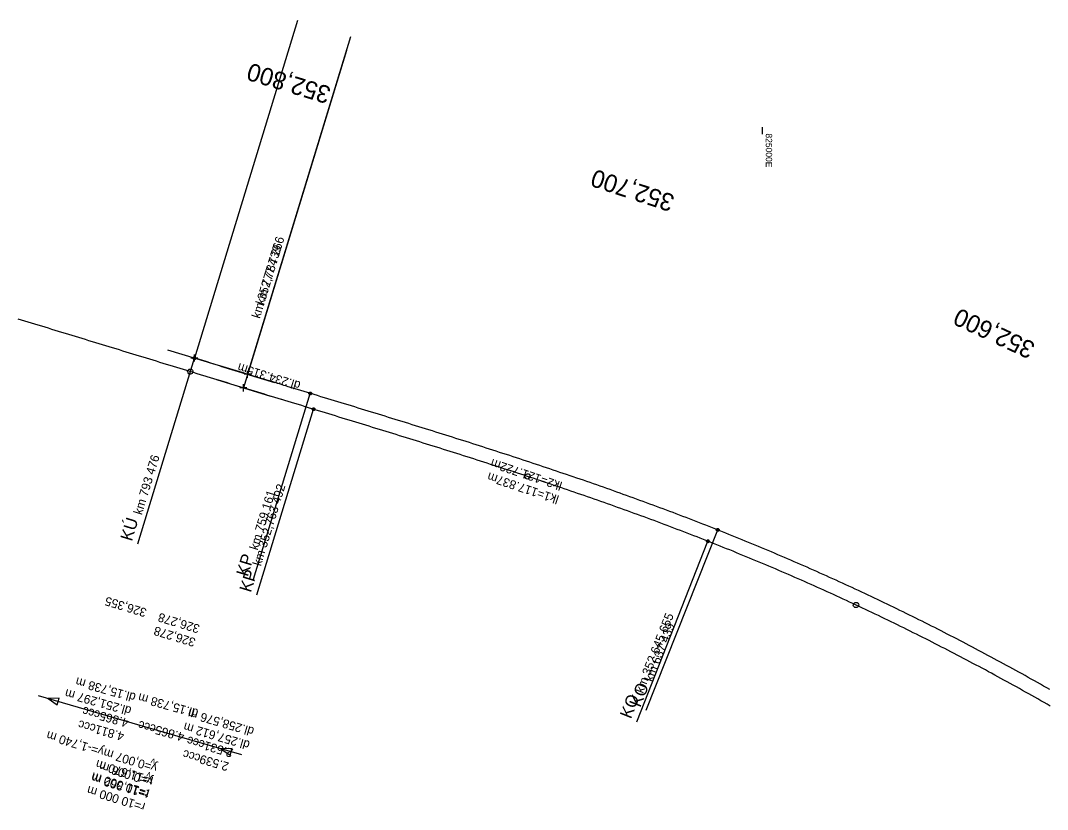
# Model space of a CAD drawing. Extents: x -825429 to 825387, y -1070027 to 1069917.
# Drawn here: x -825210.1 to -824919.2, y -1069630.4 to -1069406.8 of the extents above; entities that cross this region are included whole.
import ezdxf

# ---------------------------------------------------------------- set-up
doc = ezdxf.new("R2010")
doc.units = 0
for name, color, linetype in [('NEW KOLEJE PALKOBAR', 7, 'Continuous'), ('NEW KOLEJE VLADO', 7, 'Continuous'), ('NEW KOLEJE VLADO PROVI', 7, 'Continuous')]:
    doc.layers.add(name, color=color, linetype=linetype)

msp = doc.modelspace()

# ---------------------------------------------------------------- linework, layer by layer
at = {"layer": 'NEW KOLEJE PALKOBAR'}
for points in [[(-824918.47, -1069601.04), (-824919.33, -1069600.54), (-824920.2, -1069600.04), (-824921.07, -1069599.55), (-824921.94, -1069599.05), (-824922.81, -1069598.56), (-824923.68, -1069598.07), (-824924.55, -1069597.58), (-824925.42, -1069597.09), (-824926.3, -1069596.6), (-824927.17, -1069596.11), (-824928.04, -1069595.63), (-824928.92, -1069595.14), (-824929.79, -1069594.66), (-824930.67, -1069594.18), (-824931.55, -1069593.7), (-824932.42, -1069593.22), (-824933.3, -1069592.74), (-824934.18, -1069592.26), (-824935.06, -1069591.78), (-824935.94, -1069591.31), (-824936.82, -1069590.83), (-824937.7, -1069590.36), (-824938.58, -1069589.89), (-824939.46, -1069589.42), (-824940.35, -1069588.95), (-824941.23, -1069588.48), (-824942.11, -1069588.01), (-824943, -1069587.55), (-824943.89, -1069587.08), (-824944.77, -1069586.62), (-824945.66, -1069586.16), (-824946.55, -1069585.7), (-824947.43, -1069585.24), (-824948.32, -1069584.78), (-824949.21, -1069584.32), (-824950.1, -1069583.87), (-824950.99, -1069583.41), (-824951.88, -1069582.96), (-824952.77, -1069582.5), (-824953.67, -1069582.05), (-824954.56, -1069581.6), (-824955.45, -1069581.15), (-824956.35, -1069580.71), (-824957.24, -1069580.26), (-824958.14, -1069579.81), (-824959.03, -1069579.37), (-824959.93, -1069578.93), (-824960.83, -1069578.49), (-824961.73, -1069578.05), (-824962.62, -1069577.61), (-824963.52, -1069577.17), (-824964.42, -1069576.73), (-824965.32, -1069576.3), (-824966.22, -1069575.86), (-824967.12, -1069575.43), (-824968.03, -1069575), (-824968.93, -1069574.57), (-824969.83, -1069574.14), (-824970.74, -1069573.71), (-824971.64, -1069573.28), (-824972.54, -1069572.85), (-824973.45, -1069572.43), (-824974.36, -1069572.01), (-824975.26, -1069571.58), (-824976.17, -1069571.16), (-824977.08, -1069570.74), (-824977.99, -1069570.33), (-824978.89, -1069569.91), (-824979.8, -1069569.49), (-824980.71, -1069569.08), (-824981.62, -1069568.66), (-824982.54, -1069568.25), (-824983.45, -1069567.84), (-824984.36, -1069567.43), (-824985.27, -1069567.02), (-824986.18, -1069566.61), (-824987.1, -1069566.21), (-824988.01, -1069565.8), (-824988.93, -1069565.4), (-824989.84, -1069565), (-824990.76, -1069564.6), (-824991.68, -1069564.2), (-824992.59, -1069563.8), (-824993.51, -1069563.4), (-824994.43, -1069563), (-824995.35, -1069562.61), (-824996.27, -1069562.21), (-824997.19, -1069561.82), (-824998.11, -1069561.43), (-824999.03, -1069561.04), (-824999.95, -1069560.65), (-825000.87, -1069560.26), (-825001.79, -1069559.88), (-825002.72, -1069559.49), (-825003.64, -1069559.11), (-825004.56, -1069558.73), (-825005.49, -1069558.35), (-825006.41, -1069557.97), (-825007.34, -1069557.59), (-825008.26, -1069557.21), (-825009.19, -1069556.83), (-825010.12, -1069556.46), (-825011.04, -1069556.08), (-825011.97, -1069555.71), (-825012.9, -1069555.34), (-825013.83, -1069554.97), (-825014.76, -1069554.6), (-825015.37, -1069554.36), (-825015.69, -1069554.23), (-825016.62, -1069553.87), (-825017.55, -1069553.5), (-825018.48, -1069553.14), (-825019.41, -1069552.78), (-825020.35, -1069552.41), (-825021.28, -1069552.05), (-825022.21, -1069551.69), (-825023.15, -1069551.34), (-825024.08, -1069550.98), (-825025.02, -1069550.62), (-825025.95, -1069550.27), (-825026.89, -1069549.92), (-825027.82, -1069549.57), (-825028.76, -1069549.21), (-825029.7, -1069548.86), (-825030.63, -1069548.52), (-825031.57, -1069548.17), (-825032.51, -1069547.82), (-825033.45, -1069547.48), (-825034.39, -1069547.13), (-825035.33, -1069546.79), (-825036.26, -1069546.45), (-825037.2, -1069546.11), (-825038.15, -1069545.76), (-825039.09, -1069545.43), (-825040.03, -1069545.09), (-825040.97, -1069544.75), (-825041.91, -1069544.41), (-825042.85, -1069544.08), (-825043.79, -1069543.74), (-825044.74, -1069543.41), (-825045.68, -1069543.08), (-825046.62, -1069542.75), (-825047.57, -1069542.42), (-825048.51, -1069542.09), (-825049.46, -1069541.76), (-825050.4, -1069541.43), (-825051.35, -1069541.1), (-825052.29, -1069540.78), (-825053.24, -1069540.45), (-825054.18, -1069540.13), (-825055.13, -1069539.8), (-825056.08, -1069539.48), (-825057.02, -1069539.16), (-825057.97, -1069538.84), (-825058.92, -1069538.52), (-825059.86, -1069538.2), (-825060.81, -1069537.88), (-825061.76, -1069537.56), (-825062.71, -1069537.24), (-825063.66, -1069536.92), (-825064.6, -1069536.61), (-825065.55, -1069536.29), (-825066.5, -1069535.98), (-825067.45, -1069535.66), (-825068.4, -1069535.35), (-825069.35, -1069535.04), (-825070.3, -1069534.73), (-825071.25, -1069534.42), (-825072.2, -1069534.11), (-825073.15, -1069533.8), (-825074.1, -1069533.49), (-825075.06, -1069533.18), (-825076.01, -1069532.87), (-825076.96, -1069532.56), (-825077.91, -1069532.25), (-825078.86, -1069531.95), (-825079.81, -1069531.64), (-825080.77, -1069531.34), (-825081.72, -1069531.03), (-825082.67, -1069530.73), (-825083.62, -1069530.42), (-825084.58, -1069530.12), (-825085.53, -1069529.82), (-825086.48, -1069529.52), (-825087.44, -1069529.21), (-825088.39, -1069528.91), (-825089.34, -1069528.61), (-825090.3, -1069528.31), (-825091.25, -1069528.01), (-825092.21, -1069527.71), (-825093.16, -1069527.41), (-825094.11, -1069527.11), (-825095.07, -1069526.81), (-825096.02, -1069526.52), (-825096.98, -1069526.22), (-825097.93, -1069525.92), (-825098.89, -1069525.62), (-825099.84, -1069525.33), (-825100.8, -1069525.03), (-825101.75, -1069524.73), (-825102.71, -1069524.44), (-825103.66, -1069524.14), (-825104.62, -1069523.85), (-825105.57, -1069523.55), (-825106.53, -1069523.26), (-825107.48, -1069522.96), (-825108.44, -1069522.67), (-825109.4, -1069522.37), (-825110.35, -1069522.08), (-825111.31, -1069521.79), (-825112.26, -1069521.49), (-825113.22, -1069521.2), (-825114.18, -1069520.91), (-825115.13, -1069520.61), (-825116.09, -1069520.32), (-825117.04, -1069520.03), (-825118, -1069519.73), (-825118.96, -1069519.44), (-825119.91, -1069519.15), (-825120.87, -1069518.86), (-825121.83, -1069518.56), (-825122.78, -1069518.27), (-825123.74, -1069517.98), (-825124.69, -1069517.69), (-825125.65, -1069517.39), (-825126.61, -1069517.1), (-825127.08, -1069516.96), (-825127.56, -1069516.81), (-825128.52, -1069516.52), (-825129.48, -1069516.23), (-825130.43, -1069515.93), (-825131.39, -1069515.64), (-825132.35, -1069515.35), (-825133.3, -1069515.06), (-825134.26, -1069514.76), (-825135.21, -1069514.47), (-825136.08, -1069514.21), (-825136.17, -1069514.18), (-825137.13, -1069513.89), (-825138.08, -1069513.6), (-825139.04, -1069513.3), (-825140, -1069513.01), (-825140.95, -1069512.72), (-825141.91, -1069512.43), (-825142.86, -1069512.13), (-825143.82, -1069511.84), (-825144.78, -1069511.55), (-825145.73, -1069511.26), (-825146.69, -1069510.97), (-825146.94, -1069510.89), (-825147.65, -1069510.67), (-825148.6, -1069510.38), (-825149.56, -1069510.09), (-825150.52, -1069509.8), (-825151.47, -1069509.5), (-825152.43, -1069509.21), (-825153.38, -1069508.92), (-825154.34, -1069508.63), (-825155.3, -1069508.34), (-825156.25, -1069508.04), (-825157.21, -1069507.75), (-825157.81, -1069507.57), (-825158.17, -1069507.46), (-825159.12, -1069507.17), (-825160.08, -1069506.87), (-825161.04, -1069506.58), (-825161.99, -1069506.29), (-825162.95, -1069506), (-825163.9, -1069505.71), (-825164.86, -1069505.41), (-825165.82, -1069505.12), (-825166.77, -1069504.83), (-825167.73, -1069504.54), (-825168.69, -1069504.24), (-825169.64, -1069503.95), (-825170.6, -1069503.66), (-825171.56, -1069503.37), (-825172.51, -1069503.08), (-825173.47, -1069502.78), (-825174.42, -1069502.49), (-825175.38, -1069502.2), (-825176.34, -1069501.91), (-825177.29, -1069501.61), (-825178.25, -1069501.32), (-825179.21, -1069501.03), (-825180.16, -1069500.74), (-825181.12, -1069500.45), (-825182.08, -1069500.15), (-825183.03, -1069499.86), (-825183.99, -1069499.57), (-825184.94, -1069499.28), (-825185.9, -1069498.98), (-825186.86, -1069498.69), (-825187.81, -1069498.4), (-825188.77, -1069498.11), (-825189.73, -1069497.82), (-825190.68, -1069497.52), (-825191.64, -1069497.23), (-825192.6, -1069496.94), (-825193.55, -1069496.65), (-825194.51, -1069496.35), (-825195.46, -1069496.06), (-825196.42, -1069495.77), (-825197.38, -1069495.48), (-825198.33, -1069495.19), (-825199.29, -1069494.89), (-825200.25, -1069494.6), (-825201.2, -1069494.31), (-825202.16, -1069494.02), (-825203.12, -1069493.72), (-825204.07, -1069493.43), (-825205.03, -1069493.14), (-825205.98, -1069492.85), (-825206.94, -1069492.56), (-825207.9, -1069492.26), (-825208.85, -1069491.97), (-825209.81, -1069491.68), (-825210.77, -1069491.39)], [(-824918.58, -1069596.37), (-824919.45, -1069595.87), (-824920.32, -1069595.38), (-824921.19, -1069594.88), (-824922.06, -1069594.39), (-824922.93, -1069593.9), (-824923.8, -1069593.41), (-824924.67, -1069592.93), (-824925.55, -1069592.44), (-824926.42, -1069591.95), (-824927.3, -1069591.47), (-824928.17, -1069590.99), (-824929.05, -1069590.5), (-824929.93, -1069590.02), (-824930.8, -1069589.54), (-824931.68, -1069589.06), (-824932.56, -1069588.59), (-824933.44, -1069588.11), (-824934.32, -1069587.64), (-824935.2, -1069587.16), (-824936.08, -1069586.69), (-824936.96, -1069586.22), (-824937.85, -1069585.75), (-824938.73, -1069585.28), (-824939.61, -1069584.81), (-824940.5, -1069584.35), (-824941.38, -1069583.88), (-824942.27, -1069583.42), (-824943.15, -1069582.95), (-824944.04, -1069582.49), (-824944.93, -1069582.03), (-824945.82, -1069581.57), (-824946.71, -1069581.11), (-824947.6, -1069580.66), (-824948.49, -1069580.2), (-824949.38, -1069579.74), (-824950.27, -1069579.29), (-824951.16, -1069578.84), (-824952.05, -1069578.39), (-824952.94, -1069577.94), (-824953.84, -1069577.49), (-824954.73, -1069577.04), (-824955.63, -1069576.6), (-824956.52, -1069576.15), (-824957.42, -1069575.71), (-824958.32, -1069575.26), (-824959.21, -1069574.82), (-824960.11, -1069574.38), (-824961.01, -1069573.94), (-824961.91, -1069573.51), (-824962.81, -1069573.07), (-824963.71, -1069572.63), (-824964.61, -1069572.2), (-824965.51, -1069571.77), (-824966.41, -1069571.33), (-824967.32, -1069570.9), (-824968.22, -1069570.47), (-824969.12, -1069570.05), (-824970.03, -1069569.62), (-824970.93, -1069569.19), (-824971.84, -1069568.77), (-824972.74, -1069568.35), (-824973.65, -1069567.92), (-824974.56, -1069567.5), (-824975.46, -1069567.08), (-824976.37, -1069566.66), (-824977.28, -1069566.25), (-824978.19, -1069565.83), (-824979.1, -1069565.42), (-824980.01, -1069565), (-824980.92, -1069564.59), (-824981.83, -1069564.18), (-824982.75, -1069563.77), (-824983.66, -1069563.36), (-824984.57, -1069562.95), (-824985.49, -1069562.55), (-824986.4, -1069562.14), (-824987.31, -1069561.74), (-824988.23, -1069561.34), (-824989.15, -1069560.94), (-824990.06, -1069560.54), (-824990.98, -1069560.14), (-824991.9, -1069559.74), (-824992.82, -1069559.34), (-824993.73, -1069558.95), (-824994.65, -1069558.55), (-824995.57, -1069558.16), (-824996.49, -1069557.77), (-824997.41, -1069557.38), (-824998.34, -1069556.99), (-824999.26, -1069556.6), (-825000.18, -1069556.22), (-825001.1, -1069555.83), (-825002.03, -1069555.45), (-825002.95, -1069555.07), (-825003.87, -1069554.68), (-825004.8, -1069554.3), (-825005.72, -1069553.92), (-825006.65, -1069553.55), (-825007.58, -1069553.17), (-825008.5, -1069552.8), (-825009.43, -1069552.42), (-825010.36, -1069552.05), (-825011.29, -1069551.68), (-825012.22, -1069551.31), (-825012.62, -1069551.14), (-825013.15, -1069550.94), (-825014.08, -1069550.57), (-825015.01, -1069550.2), (-825015.94, -1069549.84), (-825016.87, -1069549.47), (-825017.8, -1069549.11), (-825018.73, -1069548.75), (-825019.66, -1069548.39), (-825020.6, -1069548.03), (-825021.53, -1069547.67), (-825022.47, -1069547.31), (-825023.4, -1069546.96), (-825024.34, -1069546.6), (-825025.27, -1069546.25), (-825026.21, -1069545.9), (-825027.14, -1069545.55), (-825028.08, -1069545.2), (-825029.02, -1069544.85), (-825029.95, -1069544.5), (-825030.89, -1069544.15), (-825031.83, -1069543.81), (-825032.77, -1069543.46), (-825033.71, -1069543.12), (-825034.65, -1069542.77), (-825035.59, -1069542.43), (-825036.53, -1069542.09), (-825037.47, -1069541.75), (-825038.41, -1069541.41), (-825039.35, -1069541.08), (-825040.29, -1069540.74), (-825041.23, -1069540.4), (-825042.18, -1069540.07), (-825043.12, -1069539.73), (-825044.06, -1069539.4), (-825045, -1069539.07), (-825045.95, -1069538.74), (-825046.89, -1069538.41), (-825047.84, -1069538.08), (-825048.78, -1069537.75), (-825049.72, -1069537.42), (-825050.67, -1069537.09), (-825051.62, -1069536.77), (-825052.56, -1069536.44), (-825053.51, -1069536.12), (-825054.45, -1069535.79), (-825055.4, -1069535.47), (-825056.35, -1069535.15), (-825057.29, -1069534.83), (-825058.24, -1069534.51), (-825059.19, -1069534.19), (-825060.14, -1069533.87), (-825061.08, -1069533.55), (-825062.03, -1069533.23), (-825062.98, -1069532.92), (-825063.93, -1069532.6), (-825064.88, -1069532.29), (-825065.83, -1069531.97), (-825066.78, -1069531.66), (-825067.73, -1069531.34), (-825068.68, -1069531.03), (-825069.63, -1069530.72), (-825070.58, -1069530.41), (-825071.53, -1069530.1), (-825072.48, -1069529.79), (-825073.43, -1069529.48), (-825074.38, -1069529.17), (-825075.33, -1069528.86), (-825076.28, -1069528.55), (-825077.23, -1069528.25), (-825078.19, -1069527.94), (-825079.14, -1069527.63), (-825080.09, -1069527.33), (-825081.04, -1069527.02), (-825082, -1069526.72), (-825082.95, -1069526.42), (-825083.9, -1069526.11), (-825084.85, -1069525.81), (-825085.81, -1069525.51), (-825086.76, -1069525.21), (-825087.71, -1069524.9), (-825088.67, -1069524.6), (-825089.62, -1069524.3), (-825090.58, -1069524), (-825091.53, -1069523.7), (-825092.48, -1069523.4), (-825093.44, -1069523.1), (-825094.39, -1069522.81), (-825095.35, -1069522.51), (-825096.3, -1069522.21), (-825097.26, -1069521.91), (-825098.21, -1069521.61), (-825099.17, -1069521.32), (-825100.12, -1069521.02), (-825101.08, -1069520.72), (-825102.03, -1069520.43), (-825102.99, -1069520.13), (-825103.94, -1069519.84), (-825104.9, -1069519.54), (-825105.85, -1069519.25), (-825106.81, -1069518.95), (-825107.76, -1069518.66), (-825108.72, -1069518.36), (-825109.68, -1069518.07), (-825110.63, -1069517.78), (-825111.59, -1069517.48), (-825112.54, -1069517.19), (-825113.5, -1069516.9), (-825114.46, -1069516.6), (-825115.41, -1069516.31), (-825116.37, -1069516.02), (-825117.32, -1069515.73), (-825118.28, -1069515.43), (-825119.24, -1069515.14), (-825120.19, -1069514.85), (-825121.15, -1069514.56), (-825122.11, -1069514.26), (-825123.06, -1069513.97), (-825124.02, -1069513.68), (-825124.98, -1069513.39), (-825125.93, -1069513.1), (-825126.89, -1069512.8), (-825127.84, -1069512.51), (-825128, -1069512.47), (-825128.8, -1069512.22), (-825129.76, -1069511.93), (-825130.71, -1069511.64), (-825131.67, -1069511.35), (-825132.63, -1069511.05), (-825133.58, -1069510.76), (-825134.54, -1069510.47), (-825134.61, -1069510.45), (-825135.5, -1069510.18), (-825136.45, -1069509.89), (-825137.41, -1069509.59), (-825138.37, -1069509.3), (-825139.32, -1069509.01), (-825140.28, -1069508.72), (-825141.24, -1069508.43), (-825142.19, -1069508.13), (-825143.15, -1069507.84), (-825144.1, -1069507.55), (-825145.06, -1069507.26), (-825145.77, -1069507.04), (-825146.02, -1069506.97), (-825146.97, -1069506.67), (-825147.93, -1069506.38), (-825148.89, -1069506.09), (-825149.84, -1069505.8), (-825150.8, -1069505.51), (-825151.76, -1069505.22), (-825152.71, -1069504.92), (-825153.67, -1069504.63), (-825154.63, -1069504.34), (-825155.58, -1069504.05), (-825156.54, -1069503.76), (-825156.93, -1069503.64), (-825157.49, -1069503.46), (-825158.45, -1069503.17), (-825159.41, -1069502.88), (-825160.36, -1069502.59), (-825160.82, -1069502.45)], [(-825162.21, -1069507.01), (-825162.44, -1069506.89), (-825162.63, -1069506.67), (-825162.73, -1069506.48), (-825162.75, -1069506.21), (-825162.67, -1069505.93), (-825162.51, -1069505.77), (-825162.31, -1069505.62), (-825162.03, -1069505.55), (-825161.77, -1069505.57), (-825161.55, -1069505.69), (-825161.35, -1069505.91), (-825161.25, -1069506.1), (-825161.23, -1069506.37), (-825161.32, -1069506.65), (-825161.47, -1069506.81), (-825161.67, -1069506.96), (-825161.96, -1069507.03), (-825162.21, -1069507.01)], [(-825066.74, -1069536.69), (-825066.96, -1069536.56), (-825067.15, -1069536.34), (-825067.25, -1069536.15), (-825067.26, -1069535.89), (-825067.17, -1069535.6), (-825067.01, -1069535.44), (-825066.8, -1069535.3), (-825066.52, -1069535.24), (-825066.27, -1069535.27), (-825066.05, -1069535.39), (-825065.86, -1069535.61), (-825065.76, -1069535.8), (-825065.74, -1069536.07), (-825065.84, -1069536.36), (-825066, -1069536.52), (-825066.2, -1069536.66), (-825066.49, -1069536.72), (-825066.74, -1069536.69)], [(-824973.77, -1069573.11), (-824973.97, -1069572.96), (-824974.14, -1069572.72), (-824974.21, -1069572.52), (-824974.19, -1069572.25), (-824974.07, -1069571.98), (-824973.89, -1069571.84), (-824973.67, -1069571.72), (-824973.38, -1069571.69), (-824973.13, -1069571.75), (-824972.93, -1069571.9), (-824972.76, -1069572.14), (-824972.69, -1069572.34), (-824972.71, -1069572.61), (-824972.83, -1069572.88), (-824973.01, -1069573.02), (-824973.23, -1069573.14), (-824973.52, -1069573.17), (-824973.77, -1069573.11)]]:
    msp.add_lwpolyline(points, dxfattribs=at)
at = {"layer": 'NEW KOLEJE VLADO'}
msp.add_lwpolyline([(-825000, -1069437), (-825000, -1069439)], dxfattribs=at)
at = {"layer": 'NEW KOLEJE VLADO PROVI'}
for p, q in [((-825160.82, -1069503.45), (-825160.82, -1069501.45)), ((-825159.82, -1069502.45), (-825161.82, -1069502.45)), ((-825144.77, -1069507.04), (-825146.77, -1069507.04)), ((-825145.77, -1069508.04), (-825145.77, -1069506.04)), ((-825145.94, -1069510.89), (-825147.94, -1069510.89)), ((-825146.94, -1069511.89), (-825146.94, -1069509.89)), ((-825199.1, -1069598.8), (-825202.26, -1069598.93)), ((-825202.26, -1069598.93), (-825199.66, -1069600.72)), ((-825199.66, -1069600.72), (-825199.1, -1069598.8)), ((-825150.14, -1069613.06), (-825153.3, -1069613.18)), ((-825153.3, -1069613.18), (-825150.69, -1069614.98)), ((-825150.69, -1069614.98), (-825150.14, -1069613.06))]:
    msp.add_line(p, q, dxfattribs=at)
for points in [[(-825131.63, -1069406.8), (-825160.82, -1069502.45)], [(-825116.58, -1069411.4), (-825145.77, -1069507.04)], [(-825117.72, -1069415.25), (-825146.94, -1069510.89)], [(-825168.47, -1069500.11), (-825153.17, -1069504.78)], [(-825160.7, -1069502.07), (-825160.58, -1069502.13), (-825160.48, -1069502.25), (-825160.43, -1069502.35), (-825160.41, -1069502.49), (-825160.46, -1069502.64), (-825160.54, -1069502.73), (-825160.65, -1069502.81), (-825160.8, -1069502.85), (-825160.94, -1069502.83), (-825161.06, -1069502.77), (-825161.16, -1069502.65), (-825161.21, -1069502.55), (-825161.23, -1069502.41), (-825161.18, -1069502.26), (-825161.1, -1069502.17), (-825160.99, -1069502.09), (-825160.84, -1069502.05), (-825160.7, -1069502.07)], [(-825176.87, -1069555.05), (-825160.82, -1069502.45)], [(-825153.42, -1069504.71), (-825138.12, -1069509.38)], [(-825154.6, -1069508.55), (-825139.29, -1069513.23)], [(-825144.05, -1069565.07), (-825128, -1069512.47)], [(-825127.88, -1069512.08), (-825127.76, -1069512.15), (-825127.66, -1069512.26), (-825127.6, -1069512.36), (-825127.59, -1069512.51), (-825127.64, -1069512.66), (-825127.72, -1069512.75), (-825127.83, -1069512.82), (-825127.98, -1069512.86), (-825128.12, -1069512.85), (-825128.24, -1069512.78), (-825128.34, -1069512.67), (-825128.39, -1069512.57), (-825128.4, -1069512.43), (-825128.36, -1069512.27), (-825128.28, -1069512.19), (-825128.17, -1069512.11), (-825128.02, -1069512.07), (-825127.88, -1069512.08)], [(-825126.96, -1069516.58), (-825126.84, -1069516.64), (-825126.74, -1069516.76), (-825126.68, -1069516.86), (-825126.67, -1069517), (-825126.72, -1069517.15), (-825126.8, -1069517.24), (-825126.91, -1069517.32), (-825127.06, -1069517.35), (-825127.19, -1069517.34), (-825127.31, -1069517.28), (-825127.42, -1069517.16), (-825127.47, -1069517.06), (-825127.48, -1069516.92), (-825127.44, -1069516.76), (-825127.35, -1069516.68), (-825127.25, -1069516.6), (-825127.1, -1069516.56), (-825126.96, -1069516.58)], [(-825143.15, -1069569.56), (-825127.08, -1069516.96)], [(-825032.92, -1069602.26), (-825012.62, -1069551.14)], [(-825012.48, -1069550.77), (-825012.36, -1069550.85), (-825012.27, -1069550.97), (-825012.22, -1069551.07), (-825012.22, -1069551.22), (-825012.28, -1069551.37), (-825012.37, -1069551.45), (-825012.48, -1069551.52), (-825012.64, -1069551.54), (-825012.77, -1069551.52), (-825012.89, -1069551.44), (-825012.98, -1069551.32), (-825013.02, -1069551.22), (-825013.03, -1069551.07), (-825012.97, -1069550.92), (-825012.88, -1069550.84), (-825012.76, -1069550.77), (-825012.61, -1069550.75), (-825012.48, -1069550.77)], [(-825035.57, -1069605.51), (-825015.37, -1069554.36)], [(-825015.22, -1069553.99), (-825015.11, -1069554.06), (-825015.01, -1069554.19), (-825014.97, -1069554.29), (-825014.97, -1069554.43), (-825015.03, -1069554.58), (-825015.11, -1069554.66), (-825015.23, -1069554.73), (-825015.38, -1069554.76), (-825015.52, -1069554.73), (-825015.63, -1069554.66), (-825015.72, -1069554.53), (-825015.77, -1069554.43), (-825015.77, -1069554.29), (-825015.71, -1069554.14), (-825015.62, -1069554.06), (-825015.51, -1069553.99), (-825015.36, -1069553.96), (-825015.22, -1069553.99)], [(-825176.17, -1069606.52), (-825204.97, -1069598.14)], [(-825147.36, -1069614.91), (-825176.17, -1069606.52)]]:
    msp.add_lwpolyline(points, dxfattribs=at)

# ---------------------------------------------------------------- texts
at = {"layer": 'NEW KOLEJE PALKOBAR'}
for s, rotation, p in [('352,800', 163.0992, (-825121.84, -1069425.73)), ('352,700', 161.7749, (-825024.5, -1069456.37)), ('352,600', 155.0025, (-824922.35, -1069498.33))]:
    msp.add_text(s, height=5, rotation=rotation, dxfattribs=at).set_placement(p)
at = {"layer": 'NEW KOLEJE VLADO'}
msp.add_text('825000E', height=1.8, rotation=270, dxfattribs=at).set_placement((-824999, -1069438.8))
at = {"layer": 'NEW KOLEJE VLADO PROVI'}
for s, height, rotation, p in [('km 352,784 266', 2.5, 73.0092, (-825142.3, -1069491.4)), ('km 777 739', 2.5, 73.0287, (-825141.13, -1069487.55)), ('dl.234.315m', 2.5, 163.0287, (-825130.56, -1069509.2)), ('km 793 476', 2.5, 73.0287, (-825175.73, -1069547.04)), ('lk2=121.722m', 2.5, 161.4664, (-825056.45, -1069537.64)), ('lk1=117.837m', 2.5, 161.4887, (-825057.36, -1069541.49)), ('km 352,763 492', 2.5, 73.0092, (-825142.01, -1069561.54)), ('km 759 161', 2.5, 73.0287, (-825142.91, -1069557.05)), ('KÚ', 3.5, 73.0287, (-825178.55, -1069554.54)), ('KP', 3.5, 73.0287, (-825145.73, -1069564.56)), ('KP', 3.5, 73.0092, (-825144.83, -1069569.05)), ('326,355', 2.5, 163.0296, (-825174.15, -1069573.53)), ('326,278', 2.5, 163.0296, (-825159.09, -1069578.12)), ('km 352,645 655', 2.5, 68.4474, (-825033.8, -1069597.61)), ('km 637 439', 2.5, 68.3417, (-825031.13, -1069594.37)), ('326,278', 2.5, 163.0101, (-825160.3, -1069581.96)), ('dl.15,738 m', 2.5, 164.4882, (-825177.24, -1069597.54)), ('KO', 3.5, 68.3417, (-825034.55, -1069601.61)), ('dl.251,297 m', 2.5, 164.4526, (-825178.48, -1069601.37)), ('dl.15,738 m', 2.5, 164.4882, (-825159.54, -1069602.04)), ('KO', 3.5, 68.4474, (-825037.2, -1069604.87)), ('4.865ccc', 2.5, 164.4882, (-825179.25, -1069604.77)), ('dl.258,576 m', 2.5, 163.7879, (-825143.72, -1069607.22)), ('4.811ccc', 2.5, 164.4526, (-825180.49, -1069608.6)), ('4.865ccc', 2.5, 164.4882, (-825163.47, -1069608.74)), ('dl.257,612 m', 2.5, 163.7709, (-825144.93, -1069611.07)), ('y=-1,740 m', 2.5, 163.0296, (-825186.19, -1069612.98)), ('2.531ccc', 2.5, 163.7879, (-825149.66, -1069613.31)), ('y=0,007 m', 2.5, 163.0296, (-825171.13, -1069617.58)), ('2.539ccc', 2.5, 163.7709, (-825150.87, -1069617.15)), ('t=11,670 m', 2.5, 163.0296, (-825172.23, -1069621.16)), ('y=0,006 m', 2.5, 163.0101, (-825172.35, -1069621.41)), ('v', 1.8, 163.0296, (-825171.74, -1069616.12)), ('r=10 000 m', 2.5, 163.0296, (-825173.32, -1069624.75)), ('t=11,362 m', 2.5, 163.0101, (-825173.45, -1069625)), ('v', 1.8, 163.0101, (-825172.95, -1069619.96)), ('r=10 000 m', 2.5, 163.0101, (-825174.54, -1069628.59))]:
    msp.add_text(s, height=height, rotation=rotation, dxfattribs=at).set_placement(p)

doc.saveas('drawing.dxf')
